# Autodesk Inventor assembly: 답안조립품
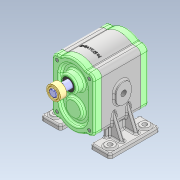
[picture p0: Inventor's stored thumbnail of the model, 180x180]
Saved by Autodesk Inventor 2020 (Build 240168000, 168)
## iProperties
Created: 2023-06
Part Number: 답안조립품
Document SubType Name: Assembly
Designer: oem
Author: oem
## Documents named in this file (11)
- C:\Users\oem\Desktop\730606V1005\답안조립품.iam
- C:\Users\oem\Desktop\730606V1005\본체.ipt
- C:\Users\oem\Desktop\730606V1005\앞커버.ipt
- C:\Users\oem\Desktop\730606V1005\뒷커버.ipt
- C:\Users\oem\Desktop\730606V1005\메인 드라이브 기어.ipt
- C:\Users\oem\Desktop\730606V1005\샤프트.ipt
- C:\Users\oem\Desktop\730606V1005\니들베어링 NA 4902.ipt
- C:\Users\oem\Desktop\730606V1005\묻힘키 6x6x40.ipt
- C:\Users\oem\Desktop\730606V1005\서브 드라이브 기어.ipt
- C:\Users\oem\Desktop\730606V1005\육각 소켓 머리 볼트 M8 x 100.ipt
- C:\Users\oem\Desktop\730606V1005\오일실 15 25 7.ipt
